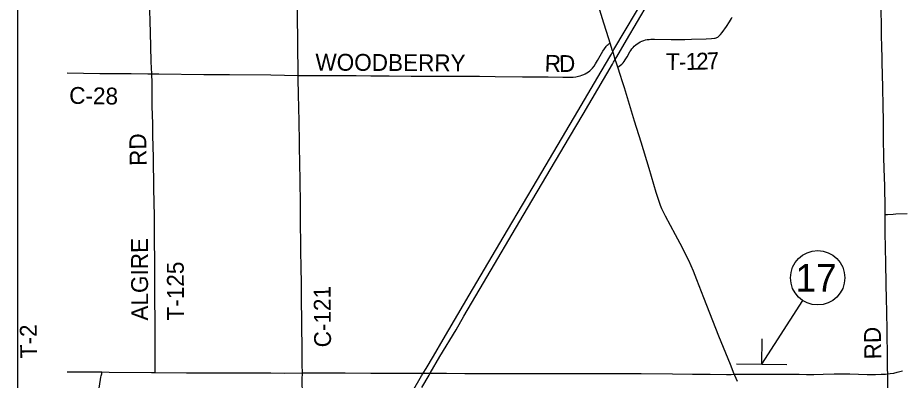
# Model space of a CAD drawing. Extents: x 40529 to 41139, y 15164 to 15584.
# Drawn here: x 40528.7 to 40618.2, y 15321.7 to 15358.4 of the extents above; entities that cross this region are included whole.
import ezdxf

# ---------------------------------------------------------------- set-up
doc = ezdxf.new("R2010")
doc.units = 0
for name, color, linetype in [('Default', 7, 'Continuous'), ('GM_X_County_Road', 7, 'Continuous'), ('GM_X_County_Road_Text', 7, 'Continuous'), ('GM_X_Interstate_Route', 7, 'Continuous'), ('GM_X_State_Route', 7, 'Continuous'), ('GM_X_Township_Road', 7, 'Continuous'), ('GM_X_Township_Road_Text', 7, 'Continuous'), ('SC_Scratch1', 7, 'Continuous'), ('SH_Data', 7, 'Continuous'), ('SH_Text', 7, 'Continuous')]:
    doc.layers.add(name, color=color, linetype=linetype)

msp = doc.modelspace()

# ---------------------------------------------------------------- linework, layer by layer
at = {"layer": 'Default'}
for p, q in [((40603.999, 15323.337), (40604.04, 15325.884)), ((40601.451, 15323.377), (40606.547, 15323.296))]:
    msp.add_line(p, q, dxfattribs=at)
at = {"layer": 'GM_X_County_Road'}
for points in [[(40557.06, 15352.563), (40557.051, 15353.293), (40557.032, 15355.102), (40557.008, 15356.31), (40556.927, 15362.258), (40556.867, 15365.056), (40556.803, 15367.946), (40556.615, 15372.978), (40556.482, 15375.68), (40556.477, 15375.813)], [(40557.06, 15352.563), (40557.162, 15352.572), (40558.279, 15352.565), (40560.326, 15352.559), (40561.629, 15352.558), (40562.932, 15352.551), (40564.421, 15352.542), (40566.281, 15352.524), (40568.514, 15352.493), (40570.097, 15352.491), (40570.935, 15352.493), (40573.545, 15352.483), (40575.408, 15352.485), (40576.99, 15352.464), (40579.776, 15352.439), (40580.707, 15352.429), (40582.383, 15352.432), (40583.872, 15352.402), (40584.523, 15352.395), (40584.894, 15352.409), (40585.171, 15352.436), (40585.444, 15352.482), (40585.623, 15352.527), (40585.799, 15352.582), (40585.969, 15352.651), (40586.135, 15352.732), (40586.294, 15352.824), (40586.445, 15352.929), (40586.589, 15353.044), (40586.723, 15353.169), (40586.848, 15353.305), (40587.02, 15353.522), (40587.178, 15353.75), (40587.373, 15354.065), (40587.925, 15355.038), (40588.074, 15355.277), (40588.237, 15355.507), (40588.297, 15355.58), (40588.362, 15355.65), (40588.438, 15355.71), (40588.522, 15355.756), (40588.658, 15355.83)], [(40533.651, 15352.825), (40536.985, 15352.773), (40539.22, 15352.759), (40540.152, 15352.753), (40541.829, 15352.726), (40542.226, 15352.725)], [(40542.226, 15352.725), (40542.946, 15352.724), (40547.505, 15352.664), (40548.6, 15352.659), (40550.09, 15352.654), (40554.276, 15352.617), (40557.06, 15352.563)], [(40557.479, 15322.434), (40557.469, 15323.259), (40557.455, 15324.732), (40557.441, 15327.425), (40557.412, 15328.356), (40557.407, 15329.195), (40557.39, 15330.126), (40557.383, 15331.431), (40557.359, 15333.202), (40557.337, 15334.694), (40557.3, 15338.424), (40557.281, 15339.542), (40557.271, 15341.964), (40557.217, 15343.665), (40557.198, 15345.411), (40557.197, 15345.598), (40557.19, 15345.785), (40557.157, 15347.927), (40557.105, 15350.632), (40557.07, 15352.213), (40557.06, 15352.563)], [(40533.651, 15322.543), (40536.427, 15322.534), (40537.189, 15322.536)], [(40537.189, 15322.536), (40537.916, 15322.526), (40542.199, 15322.471), (40542.574, 15322.469)], [(40542.574, 15322.469), (40545.738, 15322.457), (40549.555, 15322.446), (40552.256, 15322.438), (40554.303, 15322.438), (40555.7, 15322.423), (40557.479, 15322.434)], [(40558.508, 15304.131), (40558.43, 15304.425), (40558.332, 15304.752), (40558.268, 15304.959), (40558.214, 15305.138), (40558.109, 15305.476), (40558.056, 15305.644), (40557.881, 15306.207), (40557.764, 15306.556), (40557.707, 15306.85), (40557.678, 15307.139), (40557.678, 15307.489), (40557.681, 15308.063), (40557.669, 15309.554), (40557.616, 15311.798), (40557.526, 15315.615), (40557.503, 15318.878), (40557.493, 15320.237), (40557.474, 15321.767), (40557.479, 15322.434)], [(40557.479, 15322.434), (40558.382, 15322.446), (40560.612, 15322.447), (40561.822, 15322.439), (40564.43, 15322.429), (40565.175, 15322.429), (40566.2, 15322.431), (40568.995, 15322.414), (40569.361, 15322.407), (40569.718, 15322.406), (40570.142, 15322.407), (40570.436, 15322.406), (40572.07, 15322.401), (40573.932, 15322.387), (40576.066, 15322.377), (40577.182, 15322.37), (40579.228, 15322.385), (40582.115, 15322.386), (40584.071, 15322.392), (40586.397, 15322.381), (40587.884, 15322.384), (40590.11, 15322.379), (40591.787, 15322.367), (40594.953, 15322.349), (40597.002, 15322.329), (40598.772, 15322.317), (40600.449, 15322.293), (40600.914, 15322.297), (40601.219, 15322.305)], [(40601.219, 15322.305), (40601.564, 15322.319), (40602.497, 15322.318), (40607.803, 15322.3), (40608.549, 15322.295), (40609.293, 15322.289), (40610.224, 15322.31), (40611.341, 15322.347), (40611.9, 15322.359), (40612.924, 15322.348), (40614.686, 15322.294), (40615.524, 15322.292), (40616.081, 15322.307), (40616.544, 15322.33), (40616.766, 15322.35)], [(40616.766, 15322.35), (40617.005, 15322.371), (40617.37, 15322.431), (40617.733, 15322.506), (40618.274, 15322.644)]]:
    msp.add_lwpolyline(points, dxfattribs=at)
at = {"layer": 'GM_X_Interstate_Route'}
for points in [[(40588.714, 15354.625), (40588.774, 15354.728), (40588.92, 15354.987), (40589.027, 15355.179), (40592.36, 15360.837)], [(40588.892, 15353.724), (40588.999, 15353.905), (40589.171, 15354.196), (40589.317, 15354.444), (40590.313, 15356.129), (40592.533, 15359.907)], [(40567.728, 15318.988), (40569.555, 15322.137), (40569.718, 15322.406), (40570.014, 15322.895), (40570.747, 15324.133), (40571.743, 15325.818), (40574.389, 15330.317), (40578.269, 15336.902), (40581.292, 15342.045), (40585.363, 15348.949), (40587.727, 15352.965), (40588.714, 15354.625)], [(40569.583, 15320.962), (40570.331, 15322.227), (40570.436, 15322.406), (40571.416, 15324.093), (40573.042, 15326.812), (40573.843, 15328.179), (40575.832, 15331.552), (40579.849, 15338.383), (40584.538, 15346.331), (40585.911, 15348.661), (40588.892, 15353.724)]]:
    msp.add_lwpolyline(points, dxfattribs=at)
at = {"layer": 'GM_X_State_Route'}
msp.add_lwpolyline([(40601.533, 15321.579), (40601.272, 15322.171), (40601.219, 15322.305), (40600.824, 15323.303), (40599.667, 15326.156), (40598.14, 15330.06), (40597.435, 15331.883), (40597.093, 15332.743), (40596.867, 15333.279), (40596.606, 15333.84), (40595.728, 15335.54), (40595.269, 15336.418), (40594.25, 15338.308), (40594.042, 15338.721), (40593.898, 15339.063), (40593.76, 15339.394), (40593.541, 15340.011), (40593.316, 15340.727), (40592.6, 15343.129), (40591.788, 15345.812), (40591.132, 15347.942), (40590.096, 15351.309), (40589.87, 15352.019), (40589.696, 15352.55), (40589.424, 15353.396), (40589.259, 15353.928), (40589.206, 15354.085), (40589.171, 15354.196), (40588.984, 15354.776), (40588.92, 15354.987), (40588.903, 15355.044), (40588.658, 15355.83), (40588.518, 15356.282), (40588.017, 15357.876), (40587.039, 15361.083)], dxfattribs=at)
at = {"layer": 'GM_X_Township_Road'}
for points in [[(40542.226, 15352.725), (40542.182, 15353.94), (40542.133, 15355.523), (40542.058, 15358.13), (40542.03, 15359.062), (40542.013, 15359.991), (40542.001, 15361.103), (40541.984, 15362.221), (40541.976, 15363.057), (40541.934, 15364.452), (40541.931, 15365.291), (40541.935, 15366.497), (40541.919, 15367.053), (40541.894, 15367.528)], [(40616.499, 15338.489), (40616.492, 15339.715), (40616.475, 15340.804), (40616.454, 15341.242), (40616.424, 15342.354), (40616.409, 15343.004), (40616.382, 15344.397), (40616.347, 15346.072), (40616.321, 15348.027), (40616.304, 15349.424), (40616.268, 15351.378), (40616.198, 15353.891), (40616.154, 15355.942), (40616.146, 15356.129), (40616.129, 15357.897), (40616.11, 15358.92), (40616.092, 15359.846), (40616.075, 15360.309), (40616.066, 15361.427), (40616.056, 15362.638), (40616.007, 15365.525), (40615.983, 15367.2), (40615.972, 15367.653)], [(40589.424, 15353.396), (40589.571, 15353.507), (40589.714, 15353.615), (40589.823, 15353.709), (40589.954, 15353.841), (40590.071, 15353.985), (40590.176, 15354.139), (40590.365, 15354.461), (40590.641, 15354.948), (40590.739, 15355.106), (40590.847, 15355.258), (40590.966, 15355.401), (40591.096, 15355.534), (40591.235, 15355.658), (40591.384, 15355.77), (40591.541, 15355.87), (40591.705, 15355.96), (40591.874, 15356.039), (40592.048, 15356.105), (40592.227, 15356.158), (40592.409, 15356.197), (40592.593, 15356.221), (40592.779, 15356.234), (40593.152, 15356.239), (40594.83, 15356.219), (40596.227, 15356.219), (40596.878, 15356.236), (40598.366, 15356.285), (40598.924, 15356.311), (40599.202, 15356.341), (40599.293, 15356.36), (40599.382, 15356.386), (40599.47, 15356.419), (40599.554, 15356.459), (40599.633, 15356.508), (40599.704, 15356.568), (40599.834, 15356.702), (40600.004, 15356.924), (40600.429, 15357.537), (40600.737, 15358.004), (40600.929, 15358.321), (40601.013, 15358.485)], [(40542.574, 15322.469), (40542.574, 15322.655), (40542.572, 15323.585), (40542.524, 15334.023), (40542.52, 15335.606), (40542.499, 15338.307), (40542.449, 15341.102), (40542.397, 15344.268), (40542.349, 15346.501), (40542.327, 15347.805), (40542.313, 15348.455), (40542.284, 15349.568), (40542.265, 15351.243), (40542.257, 15351.988), (40542.233, 15352.547), (40542.226, 15352.725)], [(40616.499, 15338.489), (40616.752, 15338.497), (40617.325, 15338.529), (40617.581, 15338.544), (40618.74, 15338.575)], [(40616.766, 15322.35), (40616.753, 15322.865), (40616.731, 15324.723), (40616.708, 15325.932), (40616.69, 15326.86), (40616.632, 15330.115), (40616.602, 15331.231), (40616.603, 15331.511), (40616.581, 15333.552), (40616.512, 15336.658), (40616.5, 15338.332), (40616.499, 15338.489)], [(40533.651, 15304.458), (40535.13, 15308.547), (40535.239, 15308.902), (40535.351, 15309.354), (40535.524, 15310.173), (40535.623, 15310.722), (40535.702, 15311.275), (40535.995, 15313.866), (40536.16, 15315.532), (40536.316, 15316.827), (40536.504, 15318.212), (40536.773, 15320.058), (40536.966, 15321.349), (40537.033, 15321.779), (40537.074, 15321.999), (40537.106, 15322.132), (40537.157, 15322.348), (40537.189, 15322.536)], [(40617.388, 15287.456), (40617.373, 15288.667), (40617.372, 15289.598), (40617.354, 15290.713), (40617.283, 15293.315), (40617.246, 15296.387), (40617.233, 15298.064), (40617.207, 15299.738), (40617.168, 15301.787), (40617.139, 15303.647), (40617.048, 15307.824), (40617.01, 15309.407), (40616.974, 15310.896), (40616.947, 15312.384), (40616.931, 15313.687), (40616.893, 15315.73), (40616.825, 15318.614), (40616.779, 15320.928), (40616.774, 15322.034), (40616.766, 15322.35)]]:
    msp.add_lwpolyline(points, dxfattribs=at)
at = {"layer": 'SC_Scratch1'}
msp.add_lwpolyline([(40528.651, 15584.313), (41138.651, 15584.313), (41138.651, 15164.313), (40528.651, 15164.313)], close=True, dxfattribs=at)
at = {"layer": 'SH_Data'}
msp.add_line((40603.999, 15323.337), (40608.17, 15329.765), dxfattribs=at)
at = {"layer": 'SH_Text'}
msp.add_circle((40609.667, 15332.072), 2.75, dxfattribs=at)

# ---------------------------------------------------------------- texts
at = {"layer": 'GM_X_County_Road_Text'}
for s, height, rotation, p in [('WOODBERRY', 1.7063, 359.68225, (40558.798, 15353.064)), ('R', 1.706, 358.07745, (40581.999, 15352.961)), ('D', 1.706, 0.53488, (40583.479, 15352.913)), ('C-28', 1.7063, 358.96948, (40533.854, 15349.704)), ('C-121', 1.7063, 90.5438, (40560.388, 15325.038))]:
    msp.add_text(s, height=height, rotation=rotation, dxfattribs=at).set_placement(p)
at = {"layer": 'GM_X_Township_Road_Text'}
for s, height, rotation, p in [('T', 1.706, 359.53501, (40594.291, 15353.115)), ('1', 1.706, 1.39834, (40596.328, 15353.121)), ('2', 1.706, 1.45033, (40597.381, 15353.147)), ('7', 1.706, 2.87743, (40598.478, 15353.175)), ('-', 1.706, 1.34298, (40595.626, 15353.105)), ('RD', 1.7063, 90.98724, (40541.712, 15343.421)), ('ALGIRE', 1.7063, 90.18715, (40541.862, 15327.74)), ('T-125', 1.7063, 90.28072, (40545.495, 15327.756)), ('T-2', 1.7063, 91.05342, (40530.629, 15323.942)), ('RD', 1.7063, 90.96952, (40616.113, 15323.826))]:
    msp.add_text(s, height=height, rotation=rotation, dxfattribs=at).set_placement(p)
at = {"layer": 'SH_Text'}
msp.add_text('17', height=2.8, dxfattribs=at).set_placement((40607.416, 15330.672))

doc.saveas('drawing.dxf')
